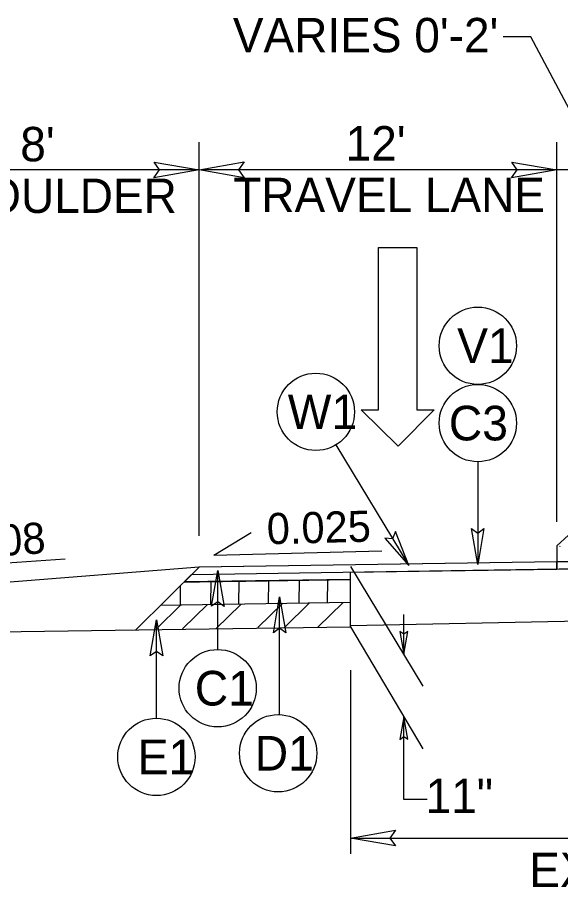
# Model space of a CAD drawing. Extents: x 2176156 to 2177167, y 76401 to 76644.
# Drawn here: x 2176800.9 to 2176819.12, y 76511.75 to 76540.91 of the extents above; entities that cross this region are included whole.
import ezdxf

# ---------------------------------------------------------------- set-up
doc = ezdxf.new("R2010")
doc.units = 0
for name, color, linetype in [('Exist Building', 7, 'Continuous'), ('Exist Roads Change in Surface', 7, 'Continuous'), ('Exist Roads Curbs', 7, 'Continuous'), ('Exist Roads EOP Other', 7, 'Continuous'), ('Exist Roads Soil', 7, 'Continuous'), ('Exist Structure Minor Culvert Topo', 7, 'Continuous'), ('Exist Structure Minor Drop Inlet', 7, 'Continuous'), ('Exist Utilities Other Pole CELL', 7, 'Continuous'), ('Model Boundary Lines Text', 7, 'Continuous'), ('Old_Level_1', 7, 'Continuous'), ('Old_Level_3', 7, 'Continuous'), ('Prop North Arrow NAD83 for Plan Sheets CELL', 7, 'Continuous'), ('Sheet Plan CELL', 7, 'Continuous')]:
    doc.layers.add(name, color=color, linetype=linetype)

msp = doc.modelspace()

# ---------------------------------------------------------------- linework, layer by layer
at = {"layer": 'Exist Building'}
for p, q in [((2176812.069, 76520.489), (2176812.069, 76522.312)), ((2176790.942, 76520.175), (2176812.069, 76520.489))]:
    msp.add_line(p, q, dxfattribs=at)
at = {"layer": 'Exist Roads Change in Surface'}
msp.add_line((2176819.096, 76523.183), (2176819.085, 76523.167), dxfattribs=at)
at = {"layer": 'Exist Roads Curbs'}
for p, q in [((2176818.989, 76522.665), (2176821.519, 76522.702)), ((2176820.798, 76522.691), (2176818.989, 76522.665)), ((2176806.989, 76522.486), (2176806.488, 76521.989)), ((2176820.846, 76522.442), (2176806.733, 76522.232)), ((2176818.989, 76522.665), (2176806.988, 76522.486)), ((2176818.989, 76522.665), (2176806.989, 76522.486)), ((2176818.989, 76522.415), (2176818.989, 76522.665)), ((2176818.989, 76522.665), (2176818.989, 76522.415)), ((2176818.989, 76522.415), (2176820.846, 76522.442)), ((2176806.488, 76521.989), (2176807, 76521.997))]:
    msp.add_line(p, q, dxfattribs=at)
msp.add_lwpolyline([(2176807, 76521.997), (2176808.563, 76522.02), (2176809.279, 76522.03), (2176810.677, 76522.051), (2176812.069, 76522.072), (2176812.069, 76522.312), (2176818.989, 76522.415)], dxfattribs=at)
at = {"layer": 'Exist Roads EOP Other'}
msp.add_line((2176806.989, 76522.486), (2176796.989, 76521.686), dxfattribs=at)
at = {"layer": 'Exist Roads Soil'}
for p, q in [((2176818.989, 76523.196), (2176819.383, 76523.559)), ((2176818.989, 76523.196), (2176818.989, 76522.415)), ((2176806.989, 76522.486), (2176804.872, 76520.382)), ((2176812.069, 76522.072), (2176806.488, 76521.989)), ((2176812.057, 76521.295), (2176805.696, 76521.201))]:
    msp.add_line(p, q, dxfattribs=at)
at = {"layer": 'Exist Structure Minor Drop Inlet'}
for p, q in [((2176813.011, 76527.761), (2176813.011, 76533.193)), ((2176813.011, 76533.193), (2176814.291, 76533.193)), ((2176814.291, 76533.193), (2176814.291, 76527.761)), ((2176813.67, 76526.539), (2176812.429, 76527.761)), ((2176812.429, 76527.761), (2176813.011, 76527.761)), ((2176814.873, 76527.761), (2176813.67, 76526.539)), ((2176814.291, 76527.761), (2176814.873, 76527.761))]:
    msp.add_line(p, q, dxfattribs=at)
at = {"layer": 'Exist Utilities Other Pole CELL'}
for p, q in [((2176807.481, 76522.881), (2176808.737, 76523.651)), ((2176807.481, 76522.881), (2176813.126, 76523.028)), ((2176797.748, 76522.448), (2176802.494, 76522.761))]:
    msp.add_line(p, q, dxfattribs=at)
at = {"layer": 'Model Boundary Lines Text'}
for p, q in [((2176806.362, 76521.213), (2176806.372, 76521.873)), ((2176807.382, 76521.235), (2176807.393, 76522.002)), ((2176808.322, 76521.242), (2176808.333, 76522.016)), ((2176809.32, 76521.266), (2176809.331, 76522.031)), ((2176810.352, 76521.279), (2176810.363, 76522.047)), ((2176811.293, 76521.286), (2176811.304, 76522.061)), ((2176805.553, 76520.41), (2176806.389, 76521.229)), ((2176806.439, 76520.415), (2176807.275, 76521.234)), ((2176807.558, 76520.419), (2176808.394, 76521.238)), ((2176808.967, 76520.46), (2176809.802, 76521.279)), ((2176809.851, 76520.464), (2176810.687, 76521.283)), ((2176810.97, 76520.468), (2176811.811, 76521.292))]:
    msp.add_line(p, q, dxfattribs=at)
at = {"layer": 'Old_Level_1'}
for points in [[(2176805.479, 76536.055), (2176806.989, 76535.795), (2176805.471, 76535.527), (2176805.664, 76535.795)], [(2176808.498, 76535.535), (2176806.989, 76535.795), (2176808.507, 76536.063), (2176808.314, 76535.795)], [(2176817.479, 76536.055), (2176818.989, 76535.795), (2176817.471, 76535.527), (2176817.664, 76535.795)], [(2176813.725, 76520.327), (2176813.857, 76519.572), (2176813.989, 76520.332), (2176813.855, 76520.235)], [(2176813.99, 76516.716), (2176813.857, 76517.47), (2176813.725, 76516.711), (2176813.859, 76516.808)], [(2176813.576, 76513.143), (2176812.066, 76513.403), (2176813.584, 76513.671), (2176813.392, 76513.403)]]:
    msp.add_lwpolyline(points, close=True, dxfattribs=at)
at = {"layer": 'Old_Level_3'}
for p, q in [((2176818.114, 76540.255), (2176817.191, 76540.255)), ((2176820.489, 76535.795), (2176818.114, 76540.255)), ((2176806.989, 76523.537), (2176806.989, 76536.723)), ((2176818.989, 76524.007), (2176818.989, 76536.723)), ((2176806.989, 76535.795), (2176796.989, 76535.795)), ((2176818.989, 76535.795), (2176807.095, 76535.795)), ((2176830.194, 76535.795), (2176818.989, 76535.795)), ((2176812.068, 76522.505), (2176814.494, 76518.497)), ((2176813.857, 76519.572), (2176813.857, 76520.9)), ((2176812.069, 76520.49), (2176814.494, 76516.395)), ((2176812.066, 76519.038), (2176812.066, 76512.874)), ((2176813.857, 76514.695), (2176813.857, 76517.47)), ((2176814.637, 76514.695), (2176813.857, 76514.695)), ((2176812.066, 76513.403), (2176838.376, 76513.403))]:
    msp.add_line(p, q, dxfattribs=at)
at = {"layer": 'Prop North Arrow NAD83 for Plan Sheets CELL'}
for p, q in [((2176811.578, 76526.58), (2176814.023, 76522.537)), ((2176816.34, 76526.016), (2176816.34, 76522.576)), ((2176807.615, 76519.724), (2176807.615, 76522.374)), ((2176809.689, 76517.543), (2176809.689, 76521.488)), ((2176805.56, 76517.421), (2176805.56, 76520.717))]:
    msp.add_line(p, q, dxfattribs=at)
for points in [[(2176813.226, 76523.457), (2176814.023, 76522.537), (2176813.582, 76523.68), (2176813.478, 76523.438)], [(2176816.547, 76523.776), (2176816.34, 76522.576), (2176816.127, 76523.782), (2176816.34, 76523.629)], [(2176807.408, 76521.174), (2176807.615, 76522.374), (2176807.828, 76521.167), (2176807.615, 76521.32)], [(2176809.482, 76520.288), (2176809.689, 76521.488), (2176809.902, 76520.282), (2176809.689, 76520.435)], [(2176805.353, 76519.517), (2176805.56, 76520.717), (2176805.773, 76519.51), (2176805.56, 76519.663)]]:
    msp.add_lwpolyline(points, close=True, dxfattribs=at)
for centre in [(2176816.34, 76529.904), (2176810.908, 76527.689), (2176816.34, 76527.312), (2176807.615, 76518.428), (2176805.56, 76516.125), (2176809.643, 76516.248)]:
    msp.add_circle(centre, 1.296, dxfattribs=at)
at = {"layer": 'Sheet Plan CELL'}
msp.add_line((2176812.069, 76520.526), (2176821.519, 76520.722), dxfattribs=at)

# ---------------------------------------------------------------- texts
at = {"layer": 'Exist Structure Minor Culvert Topo'}
for s, height, p in [("VARIES 0'-2'", 1.15334, (2176808.124, 76539.737)), ("8'", 1.1533, (2176800.994, 76536.084)), ("12'", 1.1533, (2176811.907, 76536.111)), ('SHOULDER', 1.1533, (2176797.675, 76534.354)), ('TRAVEL LANE', 1.15334, (2176808.137, 76534.381)), ("EXIST. PAVEMENT 21'", 1.15334, (2176818.066, 76511.762))]:
    msp.add_text(s, height=height, dxfattribs=at).set_placement(p)
at = {"layer": 'Exist Utilities Other Pole CELL'}
for s, rotation, p in [('0.025', 1.4932, (2176809.275, 76523.25)), ('0.08', 3.7801, (2176799.158, 76522.778))]:
    msp.add_text(s, height=1.0429, rotation=rotation, dxfattribs=at).set_placement(p)
at = {"layer": 'Prop North Arrow NAD83 for Plan Sheets CELL'}
for s, rotation, p in [('V1', 0.0003, (2176815.647, 76529.324)), ('W1', 359.9997, (2176809.965, 76527.109)), ('C3', 0.0003, (2176815.368, 76526.732)), ('C1', 0.0003, (2176806.846, 76517.848)), ('E1', 0.0003, (2176804.931, 76515.545)), ('D1', 0.0003, (2176808.857, 76515.668))]:
    msp.add_text(s, height=1.16, rotation=rotation, dxfattribs=at).set_placement(p)
msp.add_text('11"', height=1.1533, dxfattribs=at).set_placement((2176814.589, 76514.245))

doc.saveas('drawing.dxf')
